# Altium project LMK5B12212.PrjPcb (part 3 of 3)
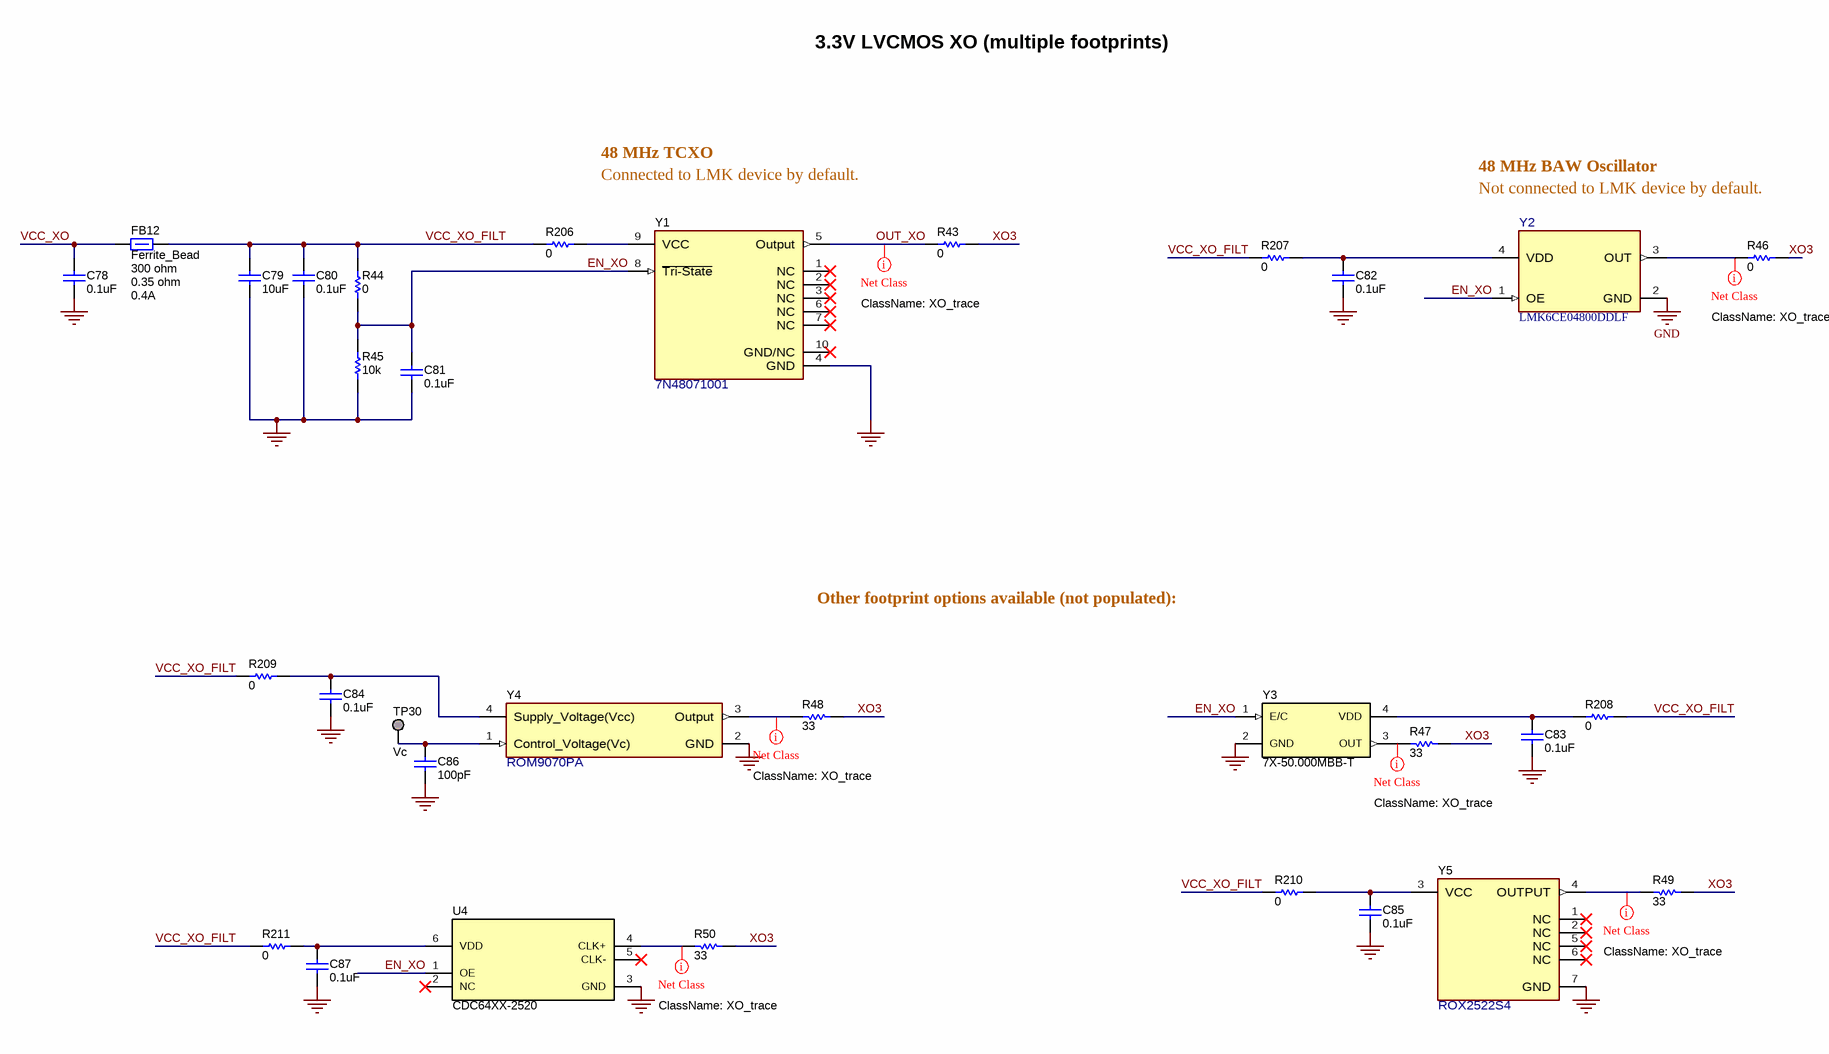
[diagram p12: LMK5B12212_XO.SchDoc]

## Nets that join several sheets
GND: LMK5B12212_DUT (38 pins), LMK5B12212_Logic (26 pins), LMK5B12212_Outputs_A (48 pins), LMK5B12212_Outputs_B (48 pins), LMK5B12212_Outputs_C (48 pins), LMK5B12212_Power (44 pins), LMK5B12212_Power_Alternate (16 pins), LMK5B12212_PowerDist (31 pins), LMK5B12212_USB2ANY (36 pins), LMK5B12212_XO (17 pins)
LDO3_IN: LMK5B12212_Power (10 pins), LMK5B12212_Power_Alternate (10 pins)
U2A_3V3: LMK5B12212_Logic (R57.2 R58.2 R59.2 R60.2), LMK5B12212_USB2ANY (13 pins)
VCC_XO: LMK5B12212_Power (5 pins), LMK5B12212_PowerDist (R15.1), LMK5B12212_XO (C78.1 FB12.2)
VDD_PLANE: LMK5B12212_Logic (R54.2), LMK5B12212_Power (5 pins), LMK5B12212_PowerDist (8 pins)
VDDGPIO: LMK5B12212_Logic (10 pins), LMK5B12212_PowerDist (NT1.1)
VDDO_PLANE: LMK5B12212_Power (5 pins), LMK5B12212_PowerDist (5 pins)
LDO1: LMK5B12212_Power (JP1.3), LMK5B12212_Power_Alternate (C2.1 U10.10 U10.11 U10.12)
LDO2: LMK5B12212_Power (JP2.3), LMK5B12212_Power_Alternate (C9.1 U11.10 U11.11 U11.12)
LMKGPIO0: LMK5B12212_DUT (U1.50), LMK5B12212_Logic (6 pins)
LMKGPIO1: LMK5B12212_DUT (U1.64), LMK5B12212_Logic (6 pins)
LMKGPIO2: LMK5B12212_DUT (U1.10), LMK5B12212_Logic (6 pins)
LMKPDN: LMK5B12212_DUT (U1.36), LMK5B12212_Logic (5 pins)
LMKSCK: LMK5B12212_DUT (U1.17), LMK5B12212_Logic (6 pins)
LMKSCS_ADD: LMK5B12212_DUT (U1.18), LMK5B12212_Logic (5 pins)
LMKSDIO: LMK5B12212_DUT (U1.16), LMK5B12212_Logic (5 pins)
OUT0_N: LMK5B12212_DUT (U1.3), LMK5B12212_Outputs_A (R10.1)
OUT0_P: LMK5B12212_DUT (U1.2), LMK5B12212_Outputs_A (R6.1)
OUT1_N: LMK5B12212_DUT (U1.4), LMK5B12212_Outputs_A (R80.1)
OUT1_P: LMK5B12212_DUT (U1.5), LMK5B12212_Outputs_A (R7.1)
OUT2_N: LMK5B12212_DUT (U1.13), LMK5B12212_Outputs_A (R84.1)
OUT2_P: LMK5B12212_DUT (U1.12), LMK5B12212_Outputs_A (R81.1)
OUT3_N: LMK5B12212_DUT (U1.14), LMK5B12212_Outputs_A (R87.1)
OUT3_P: LMK5B12212_DUT (U1.15), LMK5B12212_Outputs_A (R83.1)
OUT4_N: LMK5B12212_DUT (U1.26), LMK5B12212_Outputs_B (R93.1)
OUT4_P: LMK5B12212_DUT (U1.27), LMK5B12212_Outputs_B (R89.1)
OUT5_N: LMK5B12212_DUT (U1.25), LMK5B12212_Outputs_B (R95.1)
OUT5_P: LMK5B12212_DUT (U1.24), LMK5B12212_Outputs_B (R91.1)
OUT6_N: LMK5B12212_DUT (U1.30), LMK5B12212_Outputs_B (R100.1)
OUT6_P: LMK5B12212_DUT (U1.29), LMK5B12212_Outputs_B (R97.1)
OUT7_N: LMK5B12212_DUT (U1.31), LMK5B12212_Outputs_B (R102.1)
OUT7_P: LMK5B12212_DUT (U1.32), LMK5B12212_Outputs_B (R98.1)
OUT8_N: LMK5B12212_DUT (U1.52), LMK5B12212_Outputs_C (R107.1)
OUT8_P: LMK5B12212_DUT (U1.51), LMK5B12212_Outputs_C (R104.1)
OUT9_N: LMK5B12212_DUT (U1.53), LMK5B12212_Outputs_C (R108.1)
OUT9_P: LMK5B12212_DUT (U1.54), LMK5B12212_Outputs_C (R106.1)
OUT10_N: LMK5B12212_DUT (U1.57), LMK5B12212_Outputs_C (R114.1)
OUT10_P: LMK5B12212_DUT (U1.56), LMK5B12212_Outputs_C (R110.1)
OUT11_N: LMK5B12212_DUT (U1.58), LMK5B12212_Outputs_C (R116.1)
OUT11_P: LMK5B12212_DUT (U1.59), LMK5B12212_Outputs_C (R112.1)
U2A_I2CPU: LMK5B12212_Logic (U5.2), LMK5B12212_USB2ANY (U8.42)
U2AGPIO0: LMK5B12212_Logic (JP5.A01 R57.1), LMK5B12212_USB2ANY (J42.20 R155.1)
U2AGPIO1: LMK5B12212_Logic (JP5.A02 R58.1), LMK5B12212_USB2ANY (J42.19 R156.1)
U2AGPIO2: LMK5B12212_Logic (JP5.A04), LMK5B12212_USB2ANY (J42.18 R154.2)
U2AGPIO3: LMK5B12212_Logic (R76.1), LMK5B12212_USB2ANY (J42.17 R153.2)
U2AGPIO4: LMK5B12212_Logic (JP5.A05), LMK5B12212_USB2ANY (J42.14 R157.2)
U2AGPIO5: LMK5B12212_Logic (JP5.A06), LMK5B12212_USB2ANY (J42.13 R158.2)
U2AGPIO6: LMK5B12212_Logic (JP5.A07), LMK5B12212_USB2ANY (J42.12 R151.2)
U2AGPIO7: LMK5B12212_Logic (R52.1), LMK5B12212_USB2ANY (J42.11 R152.2)
U2AGPIO8: LMK5B12212_Logic (R64.1), LMK5B12212_USB2ANY (J42.26 R164.2)
VDD_APLL1: LMK5B12212_DUT (U1.47), LMK5B12212_PowerDist (C59.1 C60.2 FB11.2 TP18.1)
VDD_APLL2: LMK5B12212_DUT (U1.23), LMK5B12212_PowerDist (C53.1 C54.2 FB9.2 TP16.1)
VDD_DIG: LMK5B12212_DUT (U1.41 U1.44), LMK5B12212_PowerDist (C41.1 C42.2 FB5.2 TP12.1)
VDD_IN0: LMK5B12212_DUT (U1.33), LMK5B12212_PowerDist (C29.1 C30.2 FB1.2 TP8.1)
VDD_IN1: LMK5B12212_DUT (U1.37), LMK5B12212_PowerDist (C35.1 C36.2 FB3.2 TP10.1)
VDD_XO: LMK5B12212_DUT (U1.8), LMK5B12212_PowerDist (C47.1 C48.2 FB7.2 TP14.1)
VDD_XO_LMK_OPT: LMK5B12212_DUT (R4.1 R23.1), LMK5B12212_Power (JP4.7)
VDDO_0_1: LMK5B12212_DUT (U1.1), LMK5B12212_PowerDist (C32.1 C33.2 FB2.2 TP9.1)
VDDO_2_3: LMK5B12212_DUT (U1.11), LMK5B12212_PowerDist (C38.1 C39.2 FB4.2 TP11.1)
VDDO_4_TO_7: LMK5B12212_DUT (U1.28), LMK5B12212_PowerDist (C44.1 C45.2 FB6.2 TP13.1)
VDDO_8_TO_11: LMK5B12212_DUT (U1.55), LMK5B12212_PowerDist (C50.1 C51.2 FB8.2 TP15.1)
XO3: LMK5B12212_DUT (C71.2), LMK5B12212_XO (6 pins)

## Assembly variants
001: not fitted C3 C29 C32 C35 C38 C41 C44 C47 C50 C53 C59 C73 C74 C76 C77 C81 C83 C84 C85 C86 C87 C88 C91 C92 C93 C94 C95 D11 J2 J3 J5 R4 R23 R24 R28 R29 R32 R35 R36 R39 R42 R45 R46 R47 R48 R49 R50 R59 R60 R75 R78 R79 R82 R85 R86 R88 R90 R92 R94 R96 R99 R101 R103 R105 R109 R111 R113 R115 R117 R118 R119 R121 R122 R125 R127 R167 R169 R175 R176 R177 R178 R179 R180 R181 R182 R183 R184 R185 R186 R187 R188 R204 R205 R207 TP1 TP4 TP7 TP8 TP9 TP10 TP11 TP12 TP13 TP14 TP15 TP16 TP18 TP30 TP501 U4 Y3 Y4 Y5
